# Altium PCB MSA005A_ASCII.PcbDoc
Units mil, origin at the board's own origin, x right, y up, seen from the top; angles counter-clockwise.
Board outline 590 x 940 mil, 2 copper layers (Top Layer, Bottom Layer), stack 62 mil thick; 28 components, 27 nets, 81 pads, 9 vias.
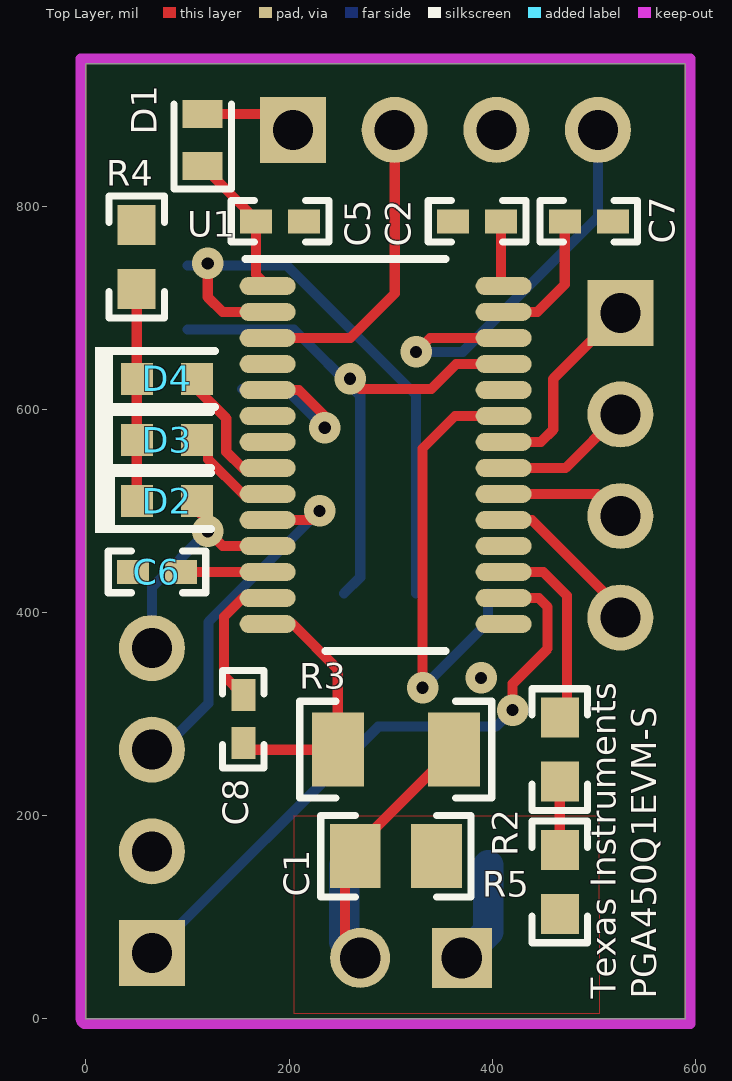
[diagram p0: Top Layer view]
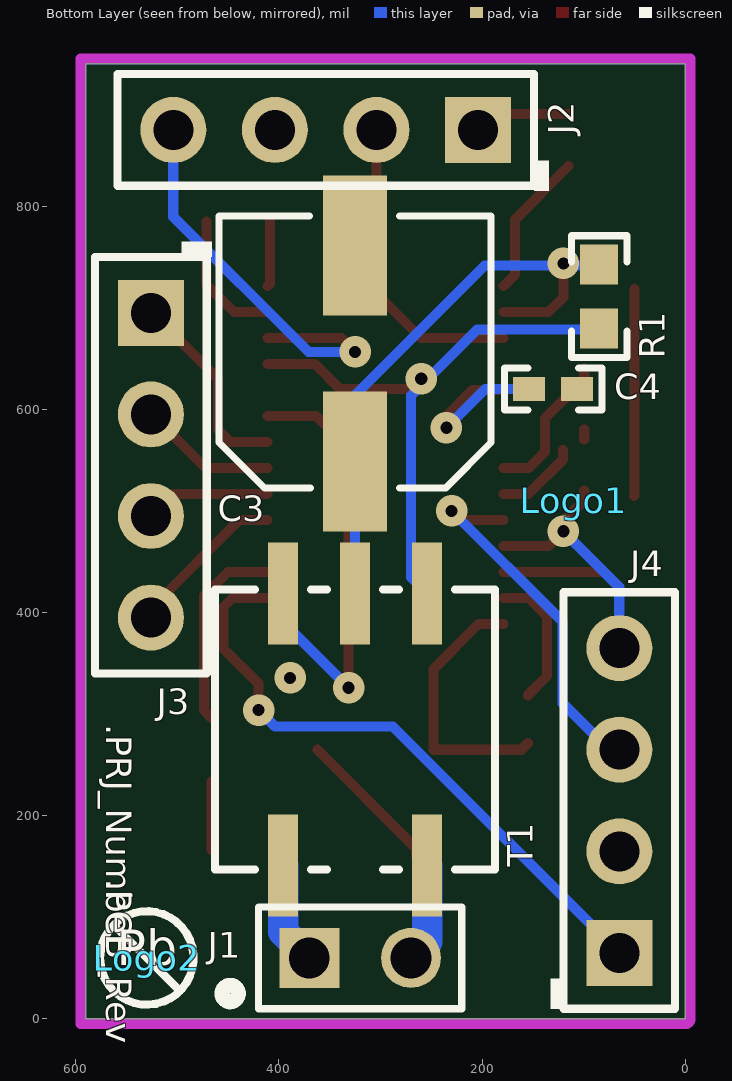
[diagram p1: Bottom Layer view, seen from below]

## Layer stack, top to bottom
Top Solder: solder mask 0.4, Solder Resist, Dk 3.5
Top Layer: signal copper 1.4
Dielectric1: core 59.2, FR-4, Dk 4.8
Bottom Layer: signal copper 1.4
Bottom Solder: solder mask 0.4, Solder Resist, Dk 3.5

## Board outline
0,0 590,0 590,940 0,940

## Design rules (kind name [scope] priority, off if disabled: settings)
AcuteAngle [All] p0: scope1count=1 scope1_0_kind=Board scope1_0_value=Board scope2count=1 scope2_0_kind=Board scope2_0_value=Board commentlength=0 minimum=4.50000000000000E+0001
AcuteAngle [All] p1: minimum=4.50000000000000E+0001 checktracksonly=FALSE
AssemblyTestPointUsage [All] p0: scope1count=1 scope1_0_kind=Board scope1_0_value=Board scope2count=1 scope2_0_kind=Board scope2_0_value=Board commentlength=0
AssemblyTestPointUsage [All] p1: valid=2
AssemblyTestpoint [All] p0: scope1count=1 scope1_0_kind=Board scope1_0_value=Board scope2count=1 scope2_0_kind=Board scope2_0_value=Board commentlength=0
Clearance Clearance_4 [All] p0 off: scope1count=1 scope1_0_kind=Board scope1_0_value=Board scope2count=1 scope2_0_kind=Board scope2_0_value=Board commentlength=70 gap=10 // Protel DXP Scope 1 Expression Was: InNamedPolygon('Top Layer-GND')
Clearance Clearance_3 [All] p0 off: scope1count=1 scope1_0_kind=Board scope1_0_value=Board scope2count=1 scope2_0_kind=Board scope2_0_value=Board commentlength=73 gap=10 // Protel DXP Scope 1 Expression Was: InNamedPolygon('Bottom Layer-GND')
Clearance Clearance_2 [All] p0 off: scope1count=1 scope1_0_kind=Board scope1_0_value=Board scope2count=1 scope2_0_kind=Board scope2_0_value=Board commentlength=77 gap=10 // Protel DXP Scope 1 Expression Was: InNamedPolygon('Top Layer-GND_SENSOR')
Clearance Clearance_1 [All] p0 off: scope1count=1 scope1_0_kind=Board scope1_0_value=Board scope2count=1 scope2_0_kind=Board scope2_0_value=Board commentlength=73 gap=10 // Protel DXP Scope 1 Expression Was: InNamedPolygon('Bottom Layer-GND')
Clearance [All] p0: scope1count=1 scope1_0_kind=Board scope1_0_value=Board scope2count=1 scope2_0_kind=Board scope2_0_value=Board commentlength=0 gap=7.87
Clearance Clearance_Poly [All] p0 off: scope1count=1 scope1_0_kind=Board scope1_0_value=Board scope2count=1 scope2_0_kind=Board scope2_0_value=Board commentlength=48 gap=25 // Protel DXP Scope 1 Expression Was: InPolygon
Clearance Clearance_BoardEdge [All] p0 off: scope1count=1 scope1_0_kind=Board scope1_0_value=Board scope2count=1 scope2_0_kind=Board scope2_0_value=Board commentlength=48 gap=25 // Protel DXP Scope 2 Expression Was: IsKeepOut
Clearance Clearance_BoardEdge_Poly [All] p0 off: scope1count=1 scope1_0_kind=Board scope1_0_value=Board scope2count=1 scope2_0_kind=Board scope2_0_value=Board commentlength=48 gap=25 // Protel DXP Scope 2 Expression Was: IsKeepOut
Clearance Clearance_BoardEdge_MountingHoles [All] p0 off: scope1count=1 scope1_0_kind=Board scope1_0_value=Board scope2count=1 scope2_0_kind=Board scope2_0_value=Board commentlength=48 gap=40 // Protel DXP Scope 2 Expression Was: IsKeepOut
Clearance Clearance_Keepouts [All] p0 off: scope1count=1 scope1_0_kind=Board scope1_0_value=Board scope2count=1 scope2_0_kind=Board scope2_0_value=Board commentlength=99 gap=0 // Protel DXP Scope 2 Expression Was: ((IsTrack Or IsArc) And Not InPoly) And IsFree and IsKeepOut
Clearance Clearance_4 [InNamedPolygon('Top Layer-GND')] p1: gap=10
Clearance Clearance_3 [InNamedPolygon('Bottom Layer-GND')] p2: gap=10
Clearance Clearance_2 [InNamedPolygon('Top Layer-GND_SENSOR')] p3: gap=10
Clearance Clearance_1 [InNamedPolygon('Bottom Layer-GND')] p4: gap=10
Clearance Clearance_Keepouts [((IsTrack Or IsArc) And Not InPoly) And IsFree and IsKeepOut vs ((IsTrack Or IsArc) And Not InPoly) And IsFree and IsKeepOut] p5: gap=0
Clearance Clearance_BoardEdge_MountingHoles [OnCopper and InComponentClass('Mounting Holes') vs IsKeepOut] p6: gap=40
Clearance Clearance_BoardEdge_Poly [OnCopper and InPoly vs IsKeepOut] p7: gap=25
Clearance Clearance_BoardEdge [OnCopper and Not InComponentClass('Logo') and not InComponentClass('FiducialMark') and not InRegion(1000,500,4000,800) and Not IsKeepout vs IsKeepOut] p8: gap=25
Clearance Clearance_Poly [InPolygon] p9: gap=25
Clearance [All] p10: gap=7.87
ComponentClearance [All] p0: scope1count=1 scope1_0_kind=Board scope1_0_value=Board scope2count=1 scope2_0_kind=Board scope2_0_value=Board commentlength=0 gap=10 collisioncheckmode=3
ComponentClearance ComponentClearance_THtoTH [All] p0 off: scope1count=1 scope1_0_kind=Board scope1_0_value=Board scope2count=1 scope2_0_kind=Board scope2_0_value=Board commentlength=54 gap=10 collisioncheckmode=3 // Protel DXP Scope 2 Expression Was: IsThruComponent
ComponentClearance ComponentClearance_THtoSMT [All] p0 off: scope1count=1 scope1_0_kind=Board scope1_0_value=Board scope2count=1 scope2_0_kind=Board scope2_0_value=Board commentlength=53 gap=10 collisioncheckmode=3 // Protel DXP Scope 2 Expression Was: IsSMTComponent
ComponentClearance ComponentClearance_SmallPassives [All] p0 off: scope1count=1 scope1_0_kind=Board scope1_0_value=Board scope2count=1 scope2_0_kind=Board scope2_0_value=Board commentlength=508 gap=20 collisioncheckmode=3 // Protel DXP Scope 2 Expression Was: HasFootprint('0201*') or HasFootprint('0402*') or HasFootprint('0508') or HasFootprint('0603*') or HasFootprint('0612') or HasFootprint('0805*') or HasFootprint('0815*') or HasFootprint('0830*') or HasFootprint('1206*') or HasFootprint('1210*') or HasFootprint('1808*') or HasFootprint('1812*') or HasFootprint('1825*') or HasFootprint('2010*') or HasFootprint('2220*') or HasFootprint('2225*') or HasFootprint('2512*') or HasFootprint('2728*') or HasFootprint('3518*')
ComponentClearance ComponentClearance_MountingHoles [All] p0: scope1count=1 scope1_0_kind=ComponentClass scope1_0_value="Mounting Holes" scope2count=1 scope2_0_kind=Board scope2_0_value=Board commentlength=0 gap=250 collisioncheckmode=3
ComponentClearance ComponentClearance_ScrewToNut [All] p0 off: scope1count=1 scope1_0_kind=Board scope1_0_value=Board scope2count=1 scope2_0_kind=Board scope2_0_value=Board commentlength=71 gap=5 collisioncheckmode=3 // Protel DXP Scope 2 Expression Was: (HasFootprint('Keystone_1902C'))
ComponentClearance ComponentClearance_Logo [All] p0: scope1count=1 scope1_0_kind=ComponentClass scope1_0_value=Logo scope2count=1 scope2_0_kind=Board scope2_0_value=Board commentlength=0 gap=50 collisioncheckmode=3
ComponentClearance ComponentClearance_Shunt [All] p0: scope1count=1 scope1_0_kind=ComponentClass scope1_0_value=Header scope2count=1 scope2_0_kind=ComponentClass scope2_0_value=Shunt commentlength=0 gap=0 collisioncheckmode=3
ComponentClearance ComponentClearance_MountingHoles_FiducialMarks [All] p0: scope1count=1 scope1_0_kind=ComponentClass scope1_0_value="Mounting Holes" scope2count=1 scope2_0_kind=ComponentClass scope2_0_value=FiducialMark commentlength=0 gap=50 collisioncheckmode=3
ComponentClearance ComponentClearance_MountingHoles_FiducialMarks [InComponentClass('Mounting Holes') vs InComponentClass('FiducialMark')] p1: gap=50 collisioncheckmode=3 verticalgap=10 showdistances=FALSE
ComponentClearance ComponentClearance_Shunt [InComponentClass('Header') vs InComponentClass('Shunt')] p2: gap=0 collisioncheckmode=3 verticalgap=0 showdistances=FALSE
ComponentClearance ComponentClearance_Logo [InComponentClass('Logo')] p3: gap=50 collisioncheckmode=3 verticalgap=10 showdistances=FALSE
ComponentClearance ComponentClearance_ScrewToNut [(HasFootprint('NY PMS 440 0025 PH')) vs (HasFootprint('Keystone_1902C'))] p4: gap=5 collisioncheckmode=3 verticalgap=10 showdistances=FALSE
ComponentClearance ComponentClearance_MountingHoles [InComponentClass('Mounting Holes')] p5: gap=250 collisioncheckmode=3 verticalgap=100000 showdistances=FALSE
ComponentClearance ComponentClearance_SmallPassives [HasFootprint('0201*') or HasFootprint('0402*') or HasFootprint('0508') or HasFootprint('0603*') or HasFootprint('0612') or HasFootprint('0805*') or HasFootprint('0815*') or HasFootprint('0830*') or HasFootprint('1206*') or HasFootprint('1210*') or HasFootprint('1808*') or HasFootprint('1812*') or HasFootprint('1825*') or HasFootprint('2010*') or HasFootprint('2220*') or HasFootprint('2225*') or HasFootprint('2512*') or HasFootprint('2728*') or HasFootprint('3518*') vs HasFootprint('0201*') or HasFootprint('0402*') or HasFootprint('0508') or HasFootprint('0603*') or HasFootprint('0612') or HasFootprint('0805*') or HasFootprint('0815*') or HasFootprint('0830*') or HasFootprint('1206*') or HasFootprint('1210*') or HasFootprint('1808*') or HasFootprint('1812*') or HasFootprint('1825*') or HasFootprint('2010*') or HasFootprint('2220*') or HasFootprint('2225*') or HasFootprint('2512*') or HasFootprint('2728*') or HasFootprint('3518*')] p6: gap=20 collisioncheckmode=3 verticalgap=10 showdistances=FALSE
ComponentClearance ComponentClearance_THtoSMT [IsThruComponent vs IsSMTComponent] p7: gap=10 collisioncheckmode=3 verticalgap=30 showdistances=FALSE
ComponentClearance ComponentClearance_THtoTH [IsThruComponent vs IsThruComponent] p8: gap=10 collisioncheckmode=3 verticalgap=30 showdistances=FALSE
ComponentClearance [All] p9: gap=10 collisioncheckmode=3 verticalgap=10 showdistances=FALSE
DiffPairsRouting [All] p0: scope1count=1 scope1_0_kind=Board scope1_0_value=Board scope2count=1 scope2_0_kind=Board scope2_0_value=Board commentlength=0
DiffPairsRouting [All] p1: maxlimit=100 minlimit=10 mostfreqgap=10 toplayer_minwidth=15 toplayer_maxwidth=15 toplayer_prefwidth=15 bottomlayer_minwidth=15 bottomlayer_maxwidth=15 bottomlayer_prefwidth=15 maxuncoupledlength=1000
FabricationTestPointUsage TestPointUsage [All] p0: scope1count=1 scope1_0_kind=Board scope1_0_value=Board scope2count=1 scope2_0_kind=Board scope2_0_value=Board commentlength=0 valid=2 allowmultiple=FALSE
FabricationTestPointUsage TestPointUsage [All] p1: valid=2 allowmultiple=FALSE
FabricationTestpoint Testpoint [All] p0: scope1count=1 scope1_0_kind=Board scope1_0_value=Board scope2count=1 scope2_0_kind=Board scope2_0_value=Board commentlength=0 side=3 testpointundercomponent=TRUE minsize=40 maxsize=100 preferedsize=60 minholesize=0 maxholesize=40 preferedholesize=32 testpointgrid=1
FabricationTestpoint Testpoint [All] p1: side=3 testpointundercomponent=TRUE minsize=40 maxsize=100 preferedsize=60 minholesize=0 maxholesize=40 preferedholesize=32 testpointgrid=1 allowsidetop=TRUE allowsidebottom=TRUE usegrid=TRUE gridtolerance=0.01
FanoutControl Fanout_Small [All] p0 off: scope1count=1 scope1_0_kind=Board scope1_0_value=Board scope2count=1 scope2_0_kind=Board scope2_0_value=Board commentlength=84 // Protel DXP Scope 1 Expression Was: (CompPinCount < 5)   Fanout_Small (Default Rule)
FanoutControl Fanout_Default [All] p0: scope1count=1 scope1_0_kind=Board scope1_0_value=Board scope2count=1 scope2_0_kind=Board scope2_0_value=Board commentlength=30 // Fanout_Default (Default Rule)
FanoutControl Fanout_SOIC [All] p0 off: scope1count=1 scope1_0_kind=Board scope1_0_value=Board scope2count=1 scope2_0_kind=Board scope2_0_value=Board commentlength=71 // Protel DXP Scope 1 Expression Was: IsSOIC   Fanout_SOIC (Default Rule)
FanoutControl Fanout_BGA [All] p0 off: scope1count=1 scope1_0_kind=Board scope1_0_value=Board scope2count=1 scope2_0_kind=Board scope2_0_value=Board commentlength=69 // Protel DXP Scope 1 Expression Was: IsBGA   Fanout_BGA (Default Rule)
FanoutControl Fanout_LCC [All] p0 off: scope1count=1 scope1_0_kind=Board scope1_0_value=Board scope2count=1 scope2_0_kind=Board scope2_0_value=Board commentlength=69 // Protel DXP Scope 1 Expression Was: IsLCC   Fanout_LCC (Default Rule)
FanoutControl Fanout_LCC [IsLCC] p1: bgadir=Out bgaviamode=Centered fanoutstyle=Auto fanoutdirection=Alternating viagrid=1 // Fanout_LCC (Default Rule)
FanoutControl Fanout_BGA [IsBGA] p2: bgadir=Out bgaviamode=Centered fanoutstyle=Auto fanoutdirection=Alternating viagrid=1 // Fanout_BGA (Default Rule)
FanoutControl Fanout_Default [All] p4: bgadir=Out bgaviamode=Centered fanoutstyle=Auto fanoutdirection=Alternating viagrid=1 // Fanout_Default (Default Rule)
FanoutControl Fanout_Small [(CompPinCount < 5)] p5: bgadir=Out bgaviamode=Centered fanoutstyle=Auto fanoutdirection=OutThenIn viagrid=1 // Fanout_Small (Default Rule)
Height [All] p0: scope1count=1 scope1_0_kind=Board scope1_0_value=Board scope2count=1 scope2_0_kind=Board scope2_0_value=Board commentlength=0
HoleSize [All] p0: scope1count=1 scope1_0_kind=Board scope1_0_value=Board scope2count=1 scope2_0_kind=Board scope2_0_value=Board commentlength=0 absolutevalues=TRUE maxlimit=251 minlimit=8 maxpercent=80.000 minpercent=20.000
HoleSize [All] p1: absolutevalues=TRUE maxlimit=251 minlimit=8 maxpercent=80.000 minpercent=20.000
HoleToHoleClearance [All] p0: scope1count=1 scope1_0_kind=Board scope1_0_value=Board scope2count=1 scope2_0_kind=Board scope2_0_value=Board commentlength=0
LayerPairs [All] p0: scope1count=1 scope1_0_kind=Board scope1_0_value=Board scope2count=1 scope2_0_kind=Board scope2_0_value=Board commentlength=0 enforce=TRUE
MinimumAnnularRing MinimumAnnularRing_ThermalPadVias [All] p0 off: scope1count=1 scope1_0_kind=Board scope1_0_value=Board scope2count=1 scope2_0_kind=Board scope2_0_value=Board commentlength=63 minimumring=5.91 // Protel DXP Scope 1 Expression Was: IsVia and InAnyComponent
MinimumAnnularRing MinimumAnnularRing_ThermalPadVias [IsVia and InAnyComponent] p1: minimumring=5.91
MinimumSolderMaskSliver [All] p0: scope1count=1 scope1_0_kind=Board scope1_0_value=Board scope2count=1 scope2_0_kind=Board scope2_0_value=Board commentlength=0
MinimumSolderMaskSliver MinimumSolderMaskSliver_Logo [All] p0: scope1count=1 scope1_0_kind=ComponentClass scope1_0_value=Logo scope2count=1 scope2_0_kind=ComponentClass scope2_0_value=Logo commentlength=0
MinimumSolderMaskSliver MinimumSolderMaskSliver_Logo [InComponentClass('Logo') vs InComponentClass('Logo')] p1: minsoldermaskwidth=0.7
MinimumSolderMaskSliver [All] p2: minsoldermaskwidth=3.94
NetAntennae [All] p0: scope1count=1 scope1_0_kind=Board scope1_0_value=Board scope2count=1 scope2_0_kind=Board scope2_0_value=Board commentlength=0
PasteMaskExpansion [All] p0: scope1count=1 scope1_0_kind=Board scope1_0_value=Board scope2count=1 scope2_0_kind=Board scope2_0_value=Board commentlength=0 expansion=0
PlaneClearance [All] p0: scope1count=1 scope1_0_kind=Board scope1_0_value=Board scope2count=1 scope2_0_kind=Board scope2_0_value=Board commentlength=0 clearance=20
PlaneConnect [All] p0: scope1count=1 scope1_0_kind=Board scope1_0_value=Board scope2count=1 scope2_0_kind=Board scope2_0_value=Board commentlength=0 planeconnectstyle=Relief reliefexpansion=10 reliefentries=4 reliefconductorwidth=10 reliefairgap=10
PlaneConnect [All] p1: planeconnectstyle=Relief reliefexpansion=10 reliefentries=4 reliefconductorwidth=10 reliefairgap=10
PolygonConnect [All] p0: scope1count=1 scope1_0_kind=Board scope1_0_value=Board scope2count=1 scope2_0_kind=Board scope2_0_value=Board commentlength=0 connectstyle=Relief reliefconductorwidth=10 reliefentries=4 polygonreliefangle="90 Angle"
PolygonConnect [All] p1: connectstyle=Relief reliefconductorwidth=10 reliefentries=4 polygonreliefangle="90 Angle" airgapwidth=10
RoutingCorners [All] p0: scope1count=1 scope1_0_kind=Board scope1_0_value=Board scope2count=1 scope2_0_kind=Board scope2_0_value=Board commentlength=0 cornerstyle=45-Degree minsetback=100 maxsetback=100
RoutingLayers [All] p0: scope1count=1 scope1_0_kind=Board scope1_0_value=Board scope2count=1 scope2_0_kind=Board scope2_0_value=Board commentlength=0 top layer=Automatic bottom layer=Automatic
RoutingPriority [All] p0: scope1count=1 scope1_0_kind=Board scope1_0_value=Board scope2count=1 scope2_0_kind=Board scope2_0_value=Board commentlength=0
RoutingTopology [All] p0: scope1count=1 scope1_0_kind=Board scope1_0_value=Board scope2count=1 scope2_0_kind=Board scope2_0_value=Board commentlength=0 topology=Shortest
RoutingVias [All] p0: scope1count=1 scope1_0_kind=Board scope1_0_value=Board scope2count=1 scope2_0_kind=Board scope2_0_value=Board commentlength=0 holewidth=16 width=34 viastyle="Through Hole" minholewidth=7.87 minwidth=26 maxholewidth=40 maxwidth=65
RoutingVias ThermalPadVias [All] p0 off: scope1count=1 scope1_0_kind=Board scope1_0_value=Board scope2count=1 scope2_0_kind=Board scope2_0_value=Board commentlength=63 holewidth=7.87 width=19.68 viastyle="Through Hole" minholewidth=7.87 minwidth=19.68 maxholewidth=12.99 maxwidth=23.62 // Protel DXP Scope 1 Expression Was: IsVia and InAnyComponent
RoutingVias ThermalPadVias [IsVia and InAnyComponent] p1: holewidth=7.87 width=19.68 viastyle="Through Hole" minholewidth=7.87 minwidth=19.68 maxholewidth=12.99 maxwidth=23.62
RoutingVias [All] p2: holewidth=16 width=34 viastyle="Through Hole" minholewidth=7.87 minwidth=26 maxholewidth=40 maxwidth=65
ShortCircuit [All] p0: scope1count=1 scope1_0_kind=Board scope1_0_value=Board scope2count=1 scope2_0_kind=Board scope2_0_value=Board commentlength=0 allowed=FALSE
SilkToBoardRegionClearance [All] p0 off: scope1count=1 scope1_0_kind=Board scope1_0_value=Board scope2count=1 scope2_0_kind=Board scope2_0_value=Board commentlength=130 // Protel DXP Scope 1 Expression Was: Not ((IsComment or IsDesignator) And (Hide <> 'False')) and not InRegion(1000,500,4000,800)
SilkToBoardRegionClearance [Not ((IsComment or IsDesignator) And (Hide <> 'False')) and not InRegion(1000,500,4000,800)] p1 off:
SilkToSilkClearance [All] p0: scope1count=1 scope1_0_kind=Board scope1_0_value=Board scope2count=1 scope2_0_kind=Board scope2_0_value=Board commentlength=0
SilkToSilkClearance SilkToSilkClearance_Pb-FreeLogo [All] p0 off: scope1count=1 scope1_0_kind=Board scope1_0_value=Board scope2count=1 scope2_0_kind=Board scope2_0_value=Board commentlength=120 // Protel DXP Scope 2 Expression Was: (HasFootprint('Pb-Free_Overlay_Medium') OR HasFootprint('Pb-Free_Overlay_Small'))
SilkToSilkClearance SilkToSilkClearance_Pb-FreeLogo [(HasFootprint('Pb-Free_Overlay_Medium') OR HasFootprint('Pb-Free_Overlay_Small')) vs (HasFootprint('Pb-Free_Overlay_Medium') OR HasFootprint('Pb-Free_Overlay_Small'))] p1: silktosilkclearance=0
SilkToSilkClearance [All] p2: silktosilkclearance=3
SilkToSolderMaskClearance "Silk to Solder Mask Opening" [All] p0: scope1count=1 scope1_0_kind=Board scope1_0_value=Board scope2count=1 scope2_0_kind=Board scope2_0_value=Board commentlength=0
SilkToSolderMaskClearance SilkToSolderMask_over-ride [All] p0 off: scope1count=1 scope1_0_kind=Board scope1_0_value=Board scope2count=1 scope2_0_kind=Board scope2_0_value=Board commentlength=66 // Protel DXP Scope 2 Expression Was: All and not On OnSilkscreen
SilkToSolderMaskClearance SilkToSolderMask_over-ride [IsPad vs All and not On OnSilkscreen] p1: minsilkscreentomaskgap=0 clearancetoexposedcopper=FALSE
SilkToSolderMaskClearance "Silk to Solder Mask Opening" [All] p2: minsilkscreentomaskgap=3 clearancetoexposedcopper=FALSE
SolderMaskExpansion [All] p0: scope1count=1 scope1_0_kind=Board scope1_0_value=Board scope2count=1 scope2_0_kind=Board scope2_0_value=Board commentlength=0 expansion=1.97
SolderMaskExpansion [All] p1: expansion=1.97
UnRoutedNet [All] p0: scope1count=1 scope1_0_kind=Board scope1_0_value=Board scope2count=1 scope2_0_kind=Board scope2_0_value=Board commentlength=0
UnpouredPolygon [All] p0: scope1count=1 scope1_0_kind=Board scope1_0_value=Board scope2count=1 scope2_0_kind=Board scope2_0_value=Board commentlength=0
UnpouredPolygon [All] p1: allowunpoured=FALSE
Width [All] p0: scope1count=1 scope1_0_kind=Board scope1_0_value=Board scope2count=1 scope2_0_kind=Board scope2_0_value=Board commentlength=0 maxlimit=100 minlimit=6 preferedwidth=10
Width [All] p1: maxlimit=100 minlimit=6 preferedwidth=10 checkconnectedcopper=TRUE
14 further rules are at their usual default settings.

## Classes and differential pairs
component class Header: J1 J2 J3 J4
component class MSA005A: C1 C2 C3 C4 C5 C6 C7 C8 D1 D2 D3 D4 J1 J2 J3 J4 R1 R2 R3 R4 R5 T1 U1
component class AssemblyNote: ZZ2 ZZ3 ZZ4
component class MSA005A_Hardware: Logo1 Logo2 ZZ2 ZZ3 ZZ4
component class Logo: Logo1

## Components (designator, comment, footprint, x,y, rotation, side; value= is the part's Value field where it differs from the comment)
C1 "GRM2165C2A152JA01D" 0805_HV 305.23,160.16 r0 top
C2 "C1005X7R1H104K050BB" 0402 385,785 r180 top
C3 "EMVA350ADA101MF80G" CAPSMT_62_F80 325,655 r90 bottom
C4 "C1005X7R1H104K050BB" 0402 130,620 r0 bottom
C5 "C1005X7R1H104K050BB" 0402 191.13,785 r0 top
C6 "C1005X7R1H104K050BB" 0402 70,440 r0 top
C7 "C1005X7R1H104K050BB" 0402 495,785 r0 top
C8 "C1005X7R1H104K050BB" 0402 155,295 r90 top
D1 "CD0603-B0240" Diode_0603 115,865 r90 top
D2 "LTST-C190GKT" LED_LTST-C190 80,510 r180 top
D3 "LTST-C191KFKT" LTST-C191_Orange 80,570 r180 top
D4 "LTST-C191KRKT" LTST-C191_Red 80,630 r180 top
J1 "PEC02SAAN" CONN_PEC02SAAN 320,60 r180 bottom
J2 "PEC04SAAN" SULLINS_PEC04SAAN 354,875 r0 bottom
J3 "PEC04SAAN" SULLINS_PEC04SAAN 526,545 r270 bottom
J4 "PEC04SAAN" SULLINS_PEC04SAAN 65,215 r90 bottom
Logo1 "Texas Instruments" TI_Symbol_Overlay_Small 110,510 r180 bottom
Logo2 "Pb-Free Symbol" Pb-Free_Overlay_Small 530,60 r180 bottom
R1 "MCR03EZPJ000" 0603 84.74,710.85 r270 bottom
R2 "CRCW0603100KJNEA" 0603 466.46,265 r90 top
R3 "CRCW12063K30JNEA" 1206 305,265 r0 top
R4 "RC0603JR-072K7L" 0603 50,750 r270 top
R5 "MCR03EZPJ000" 0603 466.46,135 r90 top
T1 "K5-R4" Mitsumi_K5-R4 325,285 r270 bottom
U1 "PGA450TPWRQ1" PW0028A_N 295,555 r0 top
ZZ2 "These assemblies are ESD sensitive, ESD precautions shall be observed." AssemblyNote 85,1329.11 r0 top
ZZ3 "These assemblies must be clean and free from flux and all contaminants. Use of no clean flux is not acceptable." AssemblyNote 85,1240.56 r0 top
ZZ4 "These assemblies must comply with workmanship standards IPC-A-610 Class 2, unless otherwise specified." AssemblyNote 85,1152 r0 top

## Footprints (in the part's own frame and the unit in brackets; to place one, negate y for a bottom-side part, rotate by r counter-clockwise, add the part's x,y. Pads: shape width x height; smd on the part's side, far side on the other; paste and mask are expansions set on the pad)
0402 [mm] "0402 from SM-752 data"
  rect 0.8x0.6 smd: 1(-0.6,0) 2(0.6,0)
  silkscreen extent -1.22,-0.52 1.22,0.52
0603 [mm] "0603 from SM-752 data"
  rect 1x0.95 smd: 1(-0.8,0) 2(0.8,0)
  silkscreen extent -1.52,-0.69 1.52,0.69
0805_HV [mil] "0805 with 30mil clearance between pads"
  rect 50x63 smd: 1(-40,0) 2(40,0)
  silkscreen extent -74,-40 74,40
1206 [mm] "1206 from SM-752 data"
  rect 1.3x1.85 smd: 1(-1.45,0) 2(1.45,0)
  silkscreen extent -2.4,-1.21 2.4,1.21
AssemblyNote [mil] "Assembly Note"
CAPSMT_62_F80 [mm] "6.3 x 7.7mm:  Chemi-Con F80"
  rect 3.5x1.6 smd: 1(-2.7,0) 2(2.7,0)
  silkscreen extent -3.36,-3.4 3.44,3.4
CONN_PEC02SAAN [mm] "SULLINS"
  rect 1.5x1.5 hole 1.016: 1(-1.27,0)
  round 1.5 hole 1.016: 2(1.27,0)
  silkscreen extent -3.45,-1.27 2.54,1.27
Diode_0603 [mm] "Based on Bourns recommended land pattern Rev 10/09"
  rect 0.7x1 smd: 1(-0.65,0) 2(0.65,0)
  silkscreen extent -1.22,-0.72 0.9,0.72
LED_LTST-C190 [mm] "Lite-On"
  rect 0.8x0.8 smd: 1(-0.75,0) 2(0.75,0)
  silkscreen extent -1.1,-0.8 1.8,0.8
LTST-C191_Orange [mm] "SMD, 2-Leads, Body 1.6x0.8mm"
  rect 0.8x0.8 smd: 1(-0.75,0) 2(0.75,0)
  silkscreen extent -1.1,-0.8 1.8,0.8
LTST-C191_Red [mm] "SMD, 2-Leads, Body1.6x0.8mm"
  rect 0.8x0.8 smd: 1(-0.75,0) 2(0.75,0)
  silkscreen extent -1.2,-0.8 1.8,0.8
Mitsumi_K5-R4 [mm] "SMD, 5-Leads, Body 7x7mm, Pitch 1.8mm"
  rect 2.55x0.75 smd: 1(-3.4,1.8) 2(-3.4,0) 3(-3.4,-1.8) 4(3.4,-1.8) 6(3.4,1.8)
  silkscreen extent -3.5,-3.5 3.5,3.5
Pb-Free_Overlay_Small [mil]
  silkscreen extent -46,-46 46,46
PW0028A_N [mm] "TSOP, 28-Leads, Body 9.7x4.4mm, Pitch 0.65mm, IPC Medium Density"
  oval 1.4x0.45 smd mask+0.025: 1(-2.95,4.225) 2(-2.95,3.575) 3(-2.95,2.925) 4(-2.95,2.275) 5(-2.95,1.625) 6(-2.95,0.975) 7(-2.95,0.325) 8(-2.95,-0.325) 9(-2.95,-0.975) 10(-2.95,-1.625) 11(-2.95,-2.275) 12(-2.95,-2.925) 13(-2.95,-3.575) 14(-2.95,-4.225) 15(2.95,-4.225) 16(2.95,-3.575) 17(2.95,-2.925) 18(2.95,-2.275) 19(2.95,-1.625) 20(2.95,-0.975) 21(2.95,-0.325) 22(2.95,0.325) 23(2.95,0.975) 24(2.95,1.625) 25(2.95,2.275) 26(2.95,2.925) 27(2.95,3.575) 28(2.95,4.225)
  silkscreen extent -3.5,-4.9 1.5,4.9
SULLINS_PEC04SAAN [mm] "SULLINS"
  rect 1.65x1.65 hole 1: 1(-3.81,0)
  round 1.65 hole 1: 2(-1.27,0) 3(1.27,0) 4(3.81,0)
  silkscreen extent -5.59,-1.4 5.21,1.52
TI_Symbol_Overlay_Small [mil]

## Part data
C1: "CAP, CERM, 1500 pF, 100 V, +/- 5%, C0G/NP0, 0805"
C2 C4 C5 C6 C7 C8: "CAP, CERM, 0.1 µF, 50 V, +/- 10%, X7R, 0402"
C3: "CAP, AL, 100 µF, 35 V, +/- 20%, SMD"
D1: "Diode, Schottky, 45 V, 0.2 A, 0603 Diode"
D2: "LED, Green, SMD"
D3: "LED, Orange, SMD"
D4: "LED, Red, SMD"
J1: "Header, 100mil, 2x1, Tin, TH"
J2 J3 J4: "Header, 100mil, 4x1, Tin, TH"
Logo1: library part TI_Logo, "Texas Instrument Corporate Signature"
Logo2: library part Pb-Free
R1 R5: "RES, 0, 5%, 0.1 W, 0603"
R2: "RES, 100 k, 5%, 0.1 W, 0603"
R3: "RES, 3.3 k, 5%, 0.25 W, 1206"
R4: "RES, 2.7 k, 5%, 0.1 W, 0603"
T1: "Transformer, TH"
U1: "ULTRASONIC-SENSOR SIGNAL CONDITIONER, PW0028A"
ZZ2 ZZ3 ZZ4: library part AssemblyNote

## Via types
v1: diameter 31, hole 12, Top Layer to Bottom Layer, tented both sides, 9 vias

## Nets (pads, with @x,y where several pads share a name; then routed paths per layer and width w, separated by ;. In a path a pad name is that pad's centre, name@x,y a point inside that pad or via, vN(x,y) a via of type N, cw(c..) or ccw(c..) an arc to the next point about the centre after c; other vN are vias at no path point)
AVDD: C2.1 U1.28 | length 64.7
  Top Layer w10: C2.1 408.62,723.86 U1.28
CIN: C6.2 U1.12 | length 95.1
  Top Layer w10: C6.2@83.78,439.84 U1.12
CS: J3.4 U1.19 | length 159.5
  Top Layer w10: U1.19 438.98,491.02 525,405 J3.4@525,395
DACO: J4.1 U1.16 | length 616.8
  Top Layer w10: U1.16 445.75,414.25 454.5,405.5 454.5,364.5 420,330 v1(420,304)
  Bottom Layer w10: J4.1 287.68,287.68 403.68,287.68 v1(420,304)
DVDD: C4.2 U1.5 | length 175.8
  Top Layer w10: U1.5 209.57,618.98 235.11,593.44 v1(235.11,581.76)
  Bottom Layer w10: C4.2 196.87,620 v1(235.11,581.76)
GND: C2.2 C3.2 C4.1 C5.2 C6.1 C7.2 J2.3 J4.2 R2.1 R4.1 R5.2 U1.4 U1.15 U1.18 U1.24 | length 67
  Top Layer w10: R5.2 R2.1
  other v1: 388.98,335.6
GND_SENSOR: C1.2 J1.1 R5.1 T1.4 | length 101.9
  Bottom Layer w30: J1.1 395.87,85.87 T1.4
GPIO1: D4.1 U1.8 | length 145.1
  Top Layer w10: D4.1@99.53,640 99.53,629.7 138.15,591.08 138.15,558.31 154.25,542.2 U1.8
GPIO2: D3.1 U1.9 | length 91.4
  Top Layer w10: D3.1@99.53,570.47 D3.1@99.53,580 ; D3.1@120.28,560 120.28,550.9 154.56,516.61 U1.9
IN: C8.2 U1.13 | length 135.6
  Top Layer w10: C8.2 136.06,337.56 136.06,396.06 154.25,414.25 U1.13
LED_CA: D2.2 D3.2 D4.2 R4.2 | length 203.8
  Top Layer w10: R4.2 50,515.35 D2.2@50.47,514.88
LIM: C8.1 R3.1 U1.14 | length 262.3
  Top Layer w10: C8.1 161.38,265 R3.1 247.91,344.31 203.56,388.66 U1.14
LIN: J2.2 U1.3 | length 304.3
  Top Layer w10: U1.3 260.16,670.16 304,714 J2.2
MAIN: D1.2 J2.1 | length 106.5
  Top Layer w10: D1.2 199.41,890.59 J2.1@215,875
OUTA: R1.2 T1.1 U1.25 | length 563.5
  Top Layer w10: v1(260,630) 270,620 340,620 364.57,644.57 U1.25
  Bottom Layer w10: R1.2@100,678.5 204.86,678.5 270,613.37 270,434.72 T1.1
OUTB: T1.3 U1.23 | length 448.2
  Top Layer w10: v1(331.4,325.87) 331.4,561.4 363.39,593.39 U1.23
  Bottom Layer w10: v1(331.4,325.87) 395.87,390.33 T1.3
RBIAS: R2.2 U1.17 | length 194.9
  Top Layer w10: U1.17 450.16,439.84 473.5,416.5 473.5,303.54 R2.2
RXD: J4.3 U1.10 | length 354.1
  Top Layer w10: U1.10 221.02,491.02 v1(230,500)
  Bottom Layer w10: J4.3@75,265 120.76,310.76 120.76,390.76 v1(230,500)
SCLK: J3.3 U1.20 | length 122.8
  Top Layer w10: U1.20 503.39,516.61 J3.3@525,495
SDI: J3.2 U1.21 | length 135.7
  Top Layer w10: U1.21 472.2,542.2 J3.2@525,595
SDO: J3.1 U1.22 | length 195.8
  Top Layer w10: U1.22 447.8,567.8 460,580 460,630 J3.1@525,695
TXD: D2.1 J4.4 U1.11 | length 251.2
  Top Layer w10: D2.1@99.53,520 99.53,510.47 120,490 v1(120,480) 134.57,465.43 U1.11
  Bottom Layer w10: J4.4 65,425 v1(120,480)
VPROG: J2.4 U1.26 | length 411.4
  Top Layer w10: v1(324.99,656.5) 338.65,670.16 U1.26
  Bottom Layer w10: v1(324.99,656.5) 370.95,656.5 504,789.55 J2.4
VPWR: C5.1 D1.1 U1.1 | length 144.5
  Top Layer w10: D1.1 167.51,786.9 C5.1 167.51,732.69 U1.1
VREF: C7.1 U1.27 | length 133.6
  Top Layer w10: U1.27 444.29,695.75 471.38,722.83 C7.1
VREG: C3.1 R1.1 T1.2 U1.2 | length 571.1
  Top Layer w10: v1(119.97,743.59) 119.97,710.43 134.66,695.75 U1.2
  Bottom Layer w10: R1.1@100,741.5 197.56,741.5 325,614.05 C3.1 T1.2
XFMR_SEC: C1.1 J1.2 R3.2 T1.6 | length 352.1
  Top Layer w10: J1.2@255,55 255,149.93 C1.1 265.23,168.14 R3.2
  Bottom Layer w30: T1.6 254.13,75.87 J1.2
pads on no net: U1.6 U1.7

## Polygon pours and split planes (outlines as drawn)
GND on Top Layer "Top Layer-GND" (solid, pour order 9): 0,0 590,0 590,940 0,940
GND_SENSOR on Top Layer "Top Layer-GND_SENSOR" (solid, pour order 8): 204.94,200.16 504.97,200.16 505.1,5 205.11,5
GND on Bottom Layer "Bottom Layer-GND" (solid, pour order 11): 0,0 590,0 590,940 0,940

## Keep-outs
Keep-Out Layer:
  lines w10: -5,0 ccw(c0,0) 0,-5 ; -5,0 ccw(c0,0) 0,-5 ; -5,0 -5,945 595,945 595,-5 0,-5
  text ".Layer_Name" at 577,-858.49 h60

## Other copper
Top Layer:
  text ".Layer_Name" at 577,-858.49 h60
Bottom Layer:
  text ".Layer_Name" at 577,-858.49 h60

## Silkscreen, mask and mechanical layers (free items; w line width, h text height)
Top Overlay:
  text "Texas Instruments" at 530,20 h42 r90
  text "PGA450Q1EVM-S" at 570,20 h42 r90
  text ".Layer_Name" at 577,-858.49 h60
Bottom Overlay:
  text ".PRJ_Number" at 570,290 h25 r90
  text ".PCB_Rev" at 570,138 h25 r90
  text ".Layer_Name" at 577,-858.49 h60
Top Paste:
  text ".Layer_Name" at 577,-858.49 h60
Bottom Paste:
  text ".Layer_Name" at 577,-858.49 h60
Top Solder:
  text ".Layer_Name" at 577,-858.49 h60
  text ".Layer_Name" at 577,-858.49 h60
Bottom Solder:
  text ".Layer_Name" at 577,-858.49 h60
Drill Guide:
  text ".Layer_Name" at 577,-858.49 h60
M1 Board Outline:
  the board outline again, w10
  text ".Layer_Name" at 577,-858.49 h60
M2 Board Dimensions:
  rectangle: 125,-400 500,-275
  rectangle: 0,-275 125,-150
  lines w7: 0,-275 1000,-275 ; 125,-400 125,-150 ; 250,-400 250,-150 ; 500,-400 500,-150 ; 750,-400 750,-150 ; 0,-400 0,-150 1000,-150 1000,-400 0,-400
  text ".Layer_Name" at 577,-858.49 h60
M3 3D STEP Top:
  text ".Layer_Name" at 577,-858.49 h60
M4 3D STEP Bottom:
  text ".Layer_Name" at 577,-858.49 h60
M5 Assembly Top:
  lines w10: -292,-930.17 6308,-930.17 ; -292,-726.83 6310,-726.83 ; -292,-523.5 -292,-1133.5 3713,-1133.5 6310,-1133.5 6310,-523.5 -291.5,-523.5 -291.5,-1133.5 1284,-1133.5 ; 2173,-1133.5 2173,-523.5 ; 3440,-726.83 3440,-523.5 ; 4280,-726.83 4280,-523.5 ; 4902,-1140 4902,-937.17
  text "COMPONENTS MARKED 'DNP' SHOULD NOT BE POPULATED." at 1153.5,-318.5 h60
  text "ASSEMBLY VARIANT:" at 1153,-434 h60
  text ".VariantName" at 2189,-434 h60
  text "PCB VIEWED FROM TOP SIDE" at -228.5,-655.67 h60
  text "BOARD #:" at 2248,-655.67 h60
  text ".PRJ_Number" at 2793.5,-655.67 h60
  text "REV:" at 3638,-655.67 h60
  text ".PCB_Rev" at 3929.5,-655.67 h60
  text "SVN REV:" at 4476,-655.67 h60
  text ".VersionControl_RevNumber" at 4982,-655.67 h60
  text "TID #:" at 2248,-859 h60
  text ".TID" at 2793.5,-859 h60
  text "PLOT NAME =" at -228.5,-1064.34 h60
  text ".plot_File_Name" at 577,-1064.34 h60
  text "GENERATED    :" at 2250,-1064.34 h60
  text ".Print_Date" at 3119.5,-1064.34 h60
  text ".Print_Time" at 3848.5,-1064.34 h60
  text "TEXAS INSTRUMENTS" at 5113,-1064.34 h60
M6 Assembly Bottom:
  lines w10: -292.5,-727.33 6309.5,-727.33 ; -290.5,-930.67 6309.5,-930.67 ; 1115.5,-1140.5 1115.5,-937.67 ; 1737.5,-727.33 1737.5,-524 ; 2577.5,-727.33 2577.5,-524 ; 3844.5,-1134 3844.5,-524 ; 4733.5,-1134 6309,-1134 6309,-524 -292.5,-524 -292.5,-1134 2304.5,-1134 6309.5,-1134 6309.5,-524
  text "COMPONENTS MARKED 'DNP' SHOULD NOT BE POPULATED." at 6102,-318 h60
  text ".VariantName" at 5058,-434 h60
  text "ASSEMBLY VARIANT:" at 6097,-434 h60
  text ".VersionControl_RevNumber" at 1035.5,-656.17 h60
  text "SVN REV:" at 1541.5,-656.17 h60
  text ".PCB_Rev" at 2088,-656.17 h60
  text "REV:" at 2379.5,-656.17 h60
  text ".PRJ_Number" at 3224,-656.17 h60
  text "BOARD #:" at 3769.5,-656.17 h60
  text "PCB VIEWED FROM BOTTOM SIDE" at 6246,-656.17 h60
  text ".TID" at 3224,-859.5 h60
  text "TID #:" at 3769.5,-859.5 h60
  text "TEXAS INSTRUMENTS" at 904.5,-1064.84 h60
  text ".Print_Time" at 2169,-1064.84 h60
  text ".Print_Date" at 2898,-1064.84 h60
  text "GENERATED    :" at 3767.5,-1064.84 h60
  text ".plot_File_Name" at 5440.5,-1064.84 h60
  text "PLOT NAME =" at 6246,-1064.84 h60
M9 Title Sheet:
  lines w10: -491.5,1041.5 -291.5,1041.5 ; -491.5,3416.5 -291.5,3416.5 ; -491.5,5791.5 -291.5,5791.5 ; 2008.5,-1333.5 2008.5,-1133.5 ; 2008.5,7966.5 2008.5,8166.5 ; 4508.5,-1333.5 4508.5,-1133.5 ; 4508.5,7966.5 4508.5,8166.5 ; 6321,-1133.5 6321,-523.5 11303.5,-523.5 ; 7008.5,-1333.5 7008.5,-1133.5 ; 7008.5,7966.5 7008.5,8166.5 ; 9508.5,-1333.5 9508.5,-1133.5 ; 9508.5,7966.5 9508.5,8166.5 ; 11303.5,-1133.5 11303.5,-523.5 ; 11303.5,-823.5 14303.5,-823.5 ; 11303.5,-223.5 14303.5,-223.5 ; 11304.5,370.5 14304.5,370.5 ; 12008.5,-1333.5 12008.5,-1133.5 ; 12008.5,7966.5 12008.5,8166.5 ; 12808.5,-1123.5 12808.5,-523.5 ; 14303.5,-523.5 11303.5,-523.5 ; 14303.5,76.5 11303.5,76.5 ; 14308.5,66.5 14308.5,-1133.5 ; 14308.5,871 11304.5,871 11303.5,871 11303.5,370.5 11303.5,76.5 ; 14308.5,1041.5 14508.5,1041.5 ; 14308.5,3416.5 14508.5,3416.5 ; 14308.5,5791.5 14508.5,5791.5 ; 11303.5,-523.5 11303.5,76.5 ; 14308.5,-1133.5 -291.5,-1133.5 -291.5,7966.5 14308.5,7966.5 14308.5,-1133.5 ; -491.5,-1333.5 14508.5,-1333.5 14508.5,8166.5 -491.5,8166.5 -491.5,-1333.5
  text "1" at 739.84,8036.5 h70
  text "2" at 3235.5,8036.5 h70
  text "3" at 5724.84,8036.5 h70
  text "4" at 8231.51,8036.5 h70
  text "5" at 10730.5,8036.5 h70
  text "6" at 13235.5,8036.5 h70
  text "A" at -416.5,6893.5 h70
  text "A" at 14383.5,6893.5 h70
  text "B" at -416.5,4513.5 h70
  text "B" at 14383.5,4513.5 h70
  text "C" at -416.5,2138.5 h70
  text "C" at 14383.5,2138.5 h70
  text "PROJECT TITLE:" at 11343.5,277.5 h45
  text ".PRJ_Title" at 11393.5,144.17 h70
  text "DESIGNED FOR:" at 11343.5,-23.5 h45
  text ".PRJ_Customer" at 11393.5,-163.5 h70
  text "D" at -416.5,-231.5 h70
  text "D" at 14383.5,-231.5 h70
  text "FILE NAME:" at 11343.5,-323.5 h45
  text ".PCB_File_Name_No_Path" at 11393.5,-443.5 h70
  text "Texas Instruments (TI) and/or its licensors do not warrant the accuracy or completeness of this specification" at 6374,-605.34 h45
  text "ENGINEER:" at 11343.5,-613.5 h45
  text "LAYOUT BY:" at 12848.5,-613.5 h45
  text "or any information contained therein. TI and/or its licensors do not warrant that this design will meet" at 6329.01,-718 h45
  text ".PRJ_Engineer" at 11393.5,-768.49 h70
  text ".PCB_Layout" at 12899,-768.49 h70
  text "the specifications, will be suitable for your application or fit for any particular purpose, or will operate in" at 6329.01,-830.67 h45
  text ".Layer_Name" at 577,-858.49 h60
  text "ALTIUM DESIGNER VERSION:" at 12848.5,-923.5 h45
  text "an implementation. TI and/or its licensors do not warrant that the design is production worthy. You should" at 6329.01,-943.33 h45
  text "completely validate and test your design implementation to confirm the system functionality for your application." at 6374,-1056 h45
  text ".print_Scale" at 11393.5,-1056.83 h70
  text ".Application_BuildNumber" at 12899,-1056.83 h70
  text "1" at 739.84,-1263.5 h70
  text "2" at 3235.5,-1263.5 h70
  text "3" at 5724.84,-1263.5 h70
  text "4" at 8231.51,-1263.5 h70
  text "5" at 10730.5,-1263.5 h70
  text "6" at 13235.5,-1263.5 h70
M10 Fab Notes:
  drawing of 189 lines, arcs and shapes, not listed
  text "DESIGN INFORMATION" at 12381.02,6028 h60
  text "MIN. TRACK WIDTH:" at 11736.46,5848 h60
  text "8" at 12832.7,5848 h60
  text "MIL" at 12987.46,5848 h60
  text "MIN. CLEARANCE:" at 11736.46,5716 h60
  text "0.2" at 12772.7,5716 h60
  text "mm" at 12987.46,5716 h60
  text "MIN. VIA PAD SIZE:" at 11736.46,5584 h60
  text "24" at 12802.71,5584 h60
  text "MIL" at 12987.46,5584 h60
  text "0.05mm (2MIL)" at 12431.46,5442.29 h60
  text "MINIMUM ANNULAR RING" at 11407.23,5438 h60
  text "EXTERNAL" at 13139.46,5438 h60
  text "PER" at 11607.23,5320 h60
  text "IPC-D-275 CLASS 2 LEVEL C" at 11827.23,5320 h60
  text "MIL, HOLES" at 13315.46,5207.71 h60
  text "+/-" at 12923,5207 h60
  text "+/-" at 13777,5207 h60
  text "REGISTRATION TOLERANCES:" at 11407.23,5202 h60
  text "METAL" at 12607,5202 h60
  text "5" at 13183.2,5202 h60
  text "3" at 14016.2,5202 h60
  text "MIL" at 14132.46,5202 h60
  text "+/-" at 13777,5089 h60
  text "HOLE SIZE TOLERANCE (UNLESS OTHERWISE SPECIFIED):" at 11407.23,5084 h60
  text "3" at 14016.2,5084 h60
  text "MIL" at 14132.46,5084 h60
  text "MATERIAL:" at 11332.46,4874.54 h60
  text "FR-4 High Tg" at 12318.9,4734.21 h60
  text "FR-408" at 11753.46,4725.64 h60
  text "OTHER" at 13241.46,4725.64 h60
  text "X" at 12164,4722 h60
  text "62 MIL (1.6mm) +/-10%" at 12073.56,4562.92 h60
  text "THICKNESS:" at 11407.23,4558.64 h60
  text "X" at 11945.4,4558.64 h60
  text "OTHER" at 13358.46,4558.64 h60
  text "TOLERANCE:" at 11407.23,4400.64 h60
  text "X" at 12246.53,4400.64 h60
  text "ANSI IPC-6012 TYPE 3 CLASS 2" at 12433.48,4400.64 h60
  text "OTHER +/-" at 12433.46,4244.64 h60
  text "BOW & TWIST:" at 11407.23,4087.64 h60
  text "X" at 12246.53,4087.64 h60
  text "ANSI IPC-6012 TYPE 3 CLASS 2" at 12433.48,4087.64 h60
  text "OTHER +/-" at 12433.46,3929.13 h60
  text "DRILLING:" at 11332.46,3790.64 h60
  text "REFERENCE:" at 11407.23,3673.64 h60
  text "X" at 12055.46,3673.64 h60
  text "AS SHOWN" at 12242.46,3673.64 h60
  text "X" at 12956.46,3673.64 h60
  text "NC_DRILL FILES" at 13093.46,3673.64 h60
  text "PTH MIN COPPER THICKNESS:" at 11407.23,3515.64 h60
  text "X" at 12757.46,3515.64 h60
  text "1MIL" at 12894.46,3515.64 h60
  text "OTHER" at 13391.46,3515.64 h60
  text "BOARD FINISH:" at 11332.46,3356.64 h60
  text "SILKSCREEN:" at 11487.68,3238.64 h60
  text "X" at 12436.46,3238.64 h60
  text "TOP" at 12562.46,3238.64 h60
  text "X" at 12946.46,3238.64 h60
  text "BOTTOM" at 13073.46,3238.64 h60
  text "SILKSCREEN COLOR:" at 11487.68,3071.64 h60
  text "X" at 12435.42,3071.64 h60
  text "WHITE" at 12562.46,3071.64 h60
  text "OTHER" at 13073.46,3071.64 h60
  text "X" at 12566.42,2912.44 h60
  text "GREEN" at 12693.46,2912.44 h60
  text "OTHER" at 13311.46,2912.44 h60
  text "SOLDER RESIST COLOR:" at 11487.68,2901.64 h60
  text "X" at 12566.42,2742.44 h60
  text "MATTE" at 12693.46,2742.44 h60
  text "SEMI-GLOSS" at 13311,2741.8 h60
  text "IMMERSION GOLD (ENIG)" at 12393.46,2553.92 h60
  text "ENEPIG" at 13731,2550.64 h60
  text "SURFACE FINISH:" at 11332.46,2549.64 h60
  text "X" at 12206.51,2549.64 h60
  text "IMM. TIN/SILVER OR EQUIV" at 11662,2392.64 h60
  text "OTHER" at 13093.46,2392.64 h60
  text "ARRAY/PANEL:" at 11332.46,2213.64 h60
  text "CUT AND TRIM PER M1 BOARD OUTLINE" at 12393.46,2209.35 h60
  text "N.C. ROUTE" at 12393.46,2057.64 h60
  text "X" at 13072.46,2057.64 h60
  text "V. SCORE" at 13259.46,2057.64 h60
  text "CERTIFICATION:" at 11332.46,1920.64 h60
  text "MATERIALS AND WORKMANSHIP FOR ALL PCBS" at 12057.46,1920.64 h60
  text "TO MEET OR EXCEED THE REQUIREMENTS OF:" at 12057.46,1822.64 h60
  text "X" at 11683.96,1686.13 h60
  text "ANSI IPC-A-600F CLASS ->" at 11822.96,1686.13 h60
  text "X" at 13462.02,1686.13 h60
  text "2" at 13580.96,1686.14 h60
  text "1" at 13265.96,1684.64 h60
  text "3" at 13934.96,1684.64 h60
  text "X" at 11686.02,1526.64 h60
  text "UL 94V-0" at 11822.96,1526.64 h60
  text "X" at 12498.02,1526.64 h60
  text "RoHS" at 12634.96,1526.64 h60
  text "OTHER" at 13279.36,1526.64 h60
  text "PER ORDER" at 13676.42,1526.64 h60
  text "ADDITIONAL REQUIREMENTS:" at 11332.46,1385.64 h60
  text "MICROSECTION:" at 11407.23,1270.64 h60
  text "YES" at 12312.96,1270.64 h60
  text "REQUIRED" at 13174.46,1114.49 h60
  text "BARE BOARD ELEC. TEST:" at 11407.23,1111.64 h60
  text "NONE" at 12712.96,1111.64 h60
  text "X" at 13047.46,1111.64 h60
  text "PER ORDER" at 13766.46,1111.64 h60
  text "MANUFACTURER'S UL:" at 11407.23,954.64 h60
  text "RAIL" at 12572.96,950.35 h60
  text "METAL" at 13064.77,950.35 h60
  text "X" at 13440,950 h60
  text "SILK" at 13576.46,950.35 h60
  text ".Layer_Name" at 577,-858.49 h60
M11 Gerber Information:
  lines w10: -292,-930.17 6308,-930.17 ; -292,-726.83 6310,-726.83 ; -292,-523.5 -292,-1133.5 3713,-1133.5 6310,-1133.5 6310,-523.5 -291.5,-523.5 -291.5,-1133.5 1284,-1133.5 ; 2173,-1133.5 2173,-523.5 ; 3440,-726.83 3440,-523.5 ; 4280,-726.83 4280,-523.5 ; 4902,-1140 4902,-937.17
  text "ALL ARTWORK VIEWED FROM TOP SIDE" at -228.5,-655.67 h60
  text "BOARD #:" at 2248,-655.67 h60
  text ".PRJ_Number" at 2793.5,-655.67 h60
  text "REV:" at 3638,-655.67 h60
  text ".PCB_Rev" at 3929.5,-655.67 h60
  text "SVN REV:" at 4476,-655.67 h60
  text ".VersionControl_RevNumber" at 4982,-655.67 h60
  text "LAYER NAME =" at -228.5,-858.49 h60
  text "TID #:" at 2248,-859 h60
  text ".TID" at 2793.5,-859 h60
  text "PLOT NAME =" at -228.5,-1064.34 h60
  text ".plot_File_Name" at 577,-1064.34 h60
  text "GENERATED    :" at 2250,-1064.34 h60
  text ".Print_Date" at 3119.5,-1064.34 h60
  text ".Print_Time" at 3848.5,-1064.34 h60
  text "TEXAS INSTRUMENTS" at 5113,-1064.34 h60
M12 Stackup:
  drawing of 191 lines, arcs and shapes, not listed
  text "Layer" at 9790.34,7830 h60
  text "Name" at 10200.26,7830 h60
  text "Material" at 11130,7830 h60
  text "Thickness" at 11989.77,7830 h60
  text "Constant" at 12639.6,7830 h60
  text "Board Layer Stack" at 13209.46,7830 h60
  text "1" at 9790.34,7710 h60
  text "Top Overlay" at 10200.26,7710 h60
  text "2" at 9790.34,7590 h60
  text "Top Solder" at 10200.26,7590 h60
  text "Solder Resist" at 11130,7590 h60
  text "0.40mil" at 11989.77,7590 h60
  text "3.5" at 12639.6,7590 h60
  text "3" at 9790.34,7470 h60
  text "Top Layer" at 10200.26,7470 h60
  text "Copper" at 11130,7470 h60
  text "1.40mil" at 11989.77,7470 h60
  text "4" at 9790.34,7350 h60
  text "Dielectric1" at 10200.26,7350 h60
  text "FR-4" at 11130,7350 h60
  text "59.20mil" at 11989.77,7350 h60
  text "4.8" at 12639.6,7350 h60
  text "5" at 9790.34,7230 h60
  text "Bottom Layer" at 10200.26,7230 h60
  text "Copper" at 11130,7230 h60
  text "1.40mil" at 11989.77,7230 h60
  text "6" at 9790.34,7110 h60
  text "Bottom Solder" at 10200.26,7110 h60
  text "Solder Resist" at 11130,7110 h60
  text "0.40mil" at 11989.77,7110 h60
  text "3.5" at 12639.6,7110 h60
  text "7" at 9790.34,6990 h60
  text "Bottom Overlay" at 10200.26,6990 h60
  text ".Layer_Name" at 577,-858.49 h60
M13 Component Bodies Top:
  text ".Layer_Name" at 577,-858.49 h60
M14 Component Bodies Bottom:
  text ".Layer_Name" at 577,-858.49 h60
M15 Courtyards Top:
  text ".Layer_Name" at 577,-858.49 h60
M16 Courtyards Bottom:
  text ".Layer_Name" at 577,-858.49 h60
Drill Drawing:
  lines w1: 1072.87,404.5 1099.69,417.91 1126.52,404.5 1113.11,431.32 1126.52,458.14 1099.69,444.73 1072.87,458.14 1086.28,431.32 1072.87,404.5 ; 1072.87,578.86 1086.28,578.86 1099.69,565.44 1113.11,578.86 1126.52,578.86 1113.11,592.27 1126.52,605.68 1113.11,605.68 1099.69,619.09 1086.28,605.68 1072.87,605.68 1086.28,592.27 1072.87,578.86 ; 1072.87,726.39 1126.52,726.39 1126.52,780.04 1072.87,780.04 1072.87,726.39
  lines w12: 1000,356.21 3300.17,356.21 ; 1000,839.05 3300.17,839.05 ; 1401.6,195.26 1401.6,1000 ; 1789.04,195.26 1789.04,1000 ; 2509.13,195.26 2509.13,1000 ; 2817.19,195.26 2817.19,1000 ; 1000,195.26 3300.17,195.26 3300.17,1000 1000,1000 1000,195.26
  text "Symbol" at 1096.57,887.34 h78.62
  text "Quantity" at 1449.88,887.34 h78.62
  text "Finished Hole Size" at 1837.32,887.34 h78.62
  text "Plated" at 2557.42,887.34 h78.62
  text "Hole Type" at 2865.47,887.34 h78.62
  text "9" at 1449.88,726.39 h65.51
  text "12.00mil (0.305mm)" at 1837.32,726.39 h65.51
  text "PTH" at 2557.42,726.39 h65.51
  text "Round" at 2865.47,726.39 h65.51
  text "12" at 1449.88,565.44 h65.51
  text "39.37mil (1.000mm)" at 1837.32,565.44 h65.51
  text "PTH" at 2557.42,565.44 h65.51
  text "Round" at 2865.47,565.44 h65.51
  text "2" at 1449.88,404.5 h65.51
  text "40.00mil (1.016mm)" at 1837.32,404.5 h65.51
  text "PTH" at 2557.42,404.5 h65.51
  text "Round" at 2865.47,404.5 h65.51
  text "23 Total" at 1449.88,243.55 h65.51
  text ".Layer_Name" at 577,-858.49 h60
